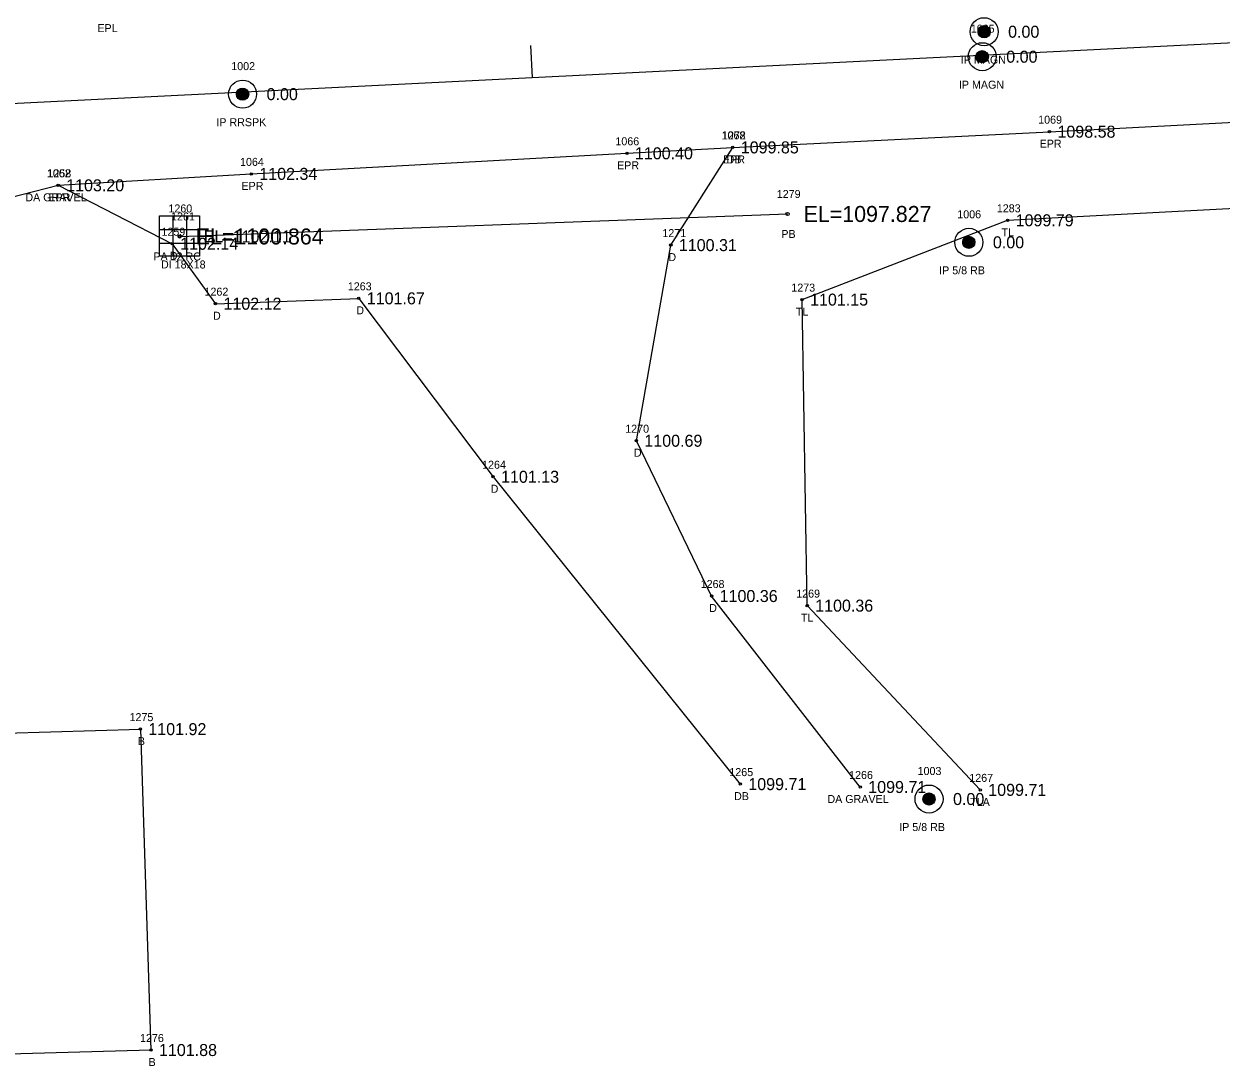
# Model space of a CAD drawing. Extents: x 1539151 to 1541799, y 1198646 to 1201165.
# Drawn here: x 1539429.9 to 1539579.5, y 1199231.9 to 1199362.1 of the extents above; entities that cross this region are included whole.
import ezdxf

# ---------------------------------------------------------------- set-up
doc = ezdxf.new("R2010")
doc.units = 0
for name, color, linetype in [('RD_EX_Bldg', 7, 'Continuous'), ('RD_EX_Bldg_txCode', 7, 'Continuous'), ('RD_EX_DR_Inlet', 7, 'Continuous'), ('RD_EX_DR_Inlet_txCode', 7, 'Continuous'), ('RD_EX_DR_Pipe', 7, 'Continuous'), ('RD_EX_DR_Pipe_txCode', 7, 'Continuous'), ('RD_EX_Driveway', 7, 'Continuous'), ('RD_EX_Driveway_txCode', 7, 'Continuous'), ('RD_EX_DV_Prop_txCode', 7, 'Continuous'), ('RD_EX_DV_PropPin', 7, 'Continuous'), ('RD_EX_Road', 7, 'Continuous'), ('RD_EX_Road_txCode', 7, 'Continuous'), ('RD_EX_TX_Bldg_ELEV', 7, 'Continuous'), ('RD_EX_TX_DR_Inlet_ELEV', 7, 'Continuous'), ('RD_EX_TX_Driveway_ELEV', 7, 'Continuous'), ('RD_EX_TX_DV_Prop_ELEV', 7, 'Continuous'), ('RD_EX_TX_Road_ELEV', 7, 'Continuous'), ('RD_EX_TX_VEG_ELEV', 7, 'Continuous'), ('RD_EX_VEG', 7, 'Continuous'), ('RD_EX_VEG_txCode', 7, 'Continuous'), ('RD_HC_Cl', 7, 'Continuous'), ('RD_HC_Data_Tic', 7, 'Continuous'), ('RD_SMD_Locator', 7, 'Continuous'), ('RD_TX_Pipe_ElevEX', 7, 'Continuous')]:
    doc.layers.add(name, color=color, linetype=linetype)

msp = doc.modelspace()

# ---------------------------------------------------------------- linework, layer by layer
at = {"layer": 'RD_EX_Bldg'}
msp.add_lwpolyline([(1539416.25, 1199273.16), (1539444.4, 1199273.98), (1539445.73, 1199233.89), (1539417.59, 1199233.06), (1539416.25, 1199273.16)], dxfattribs=at)
at = {"layer": 'RD_EX_DR_Inlet'}
for p, q in [((1539448.48, 1199338.09), (1539448.48, 1199333.09)), ((1539450.18, 1199338.09), (1539450.18, 1199333.09)), ((1539446.78, 1199336.39), (1539451.78, 1199336.39)), ((1539446.78, 1199334.69), (1539451.78, 1199334.69))]:
    msp.add_line(p, q, dxfattribs=at)
msp.add_lwpolyline([(1539446.78, 1199333.09), (1539446.78, 1199338.09), (1539451.78, 1199338.09), (1539451.78, 1199333.09)], close=True, dxfattribs=at)
at = {"layer": 'RD_EX_DR_Pipe'}
msp.add_line((1539449.32, 1199335.53), (1539525.29, 1199338.34), dxfattribs=at)
at = {"layer": 'RD_EX_Driveway'}
for points in [[(1539534.37, 1199266.75), (1539515.8, 1199290.61), (1539506.39, 1199310.01), (1539510.7, 1199334.45), (1539518.44, 1199346.66)], [(1539434.13, 1199341.92), (1539448.38, 1199334.62), (1539453.79, 1199327.13), (1539471.7, 1199327.8), (1539488.48, 1199305.51), (1539519.38, 1199267.11)]]:
    msp.add_lwpolyline(points, dxfattribs=at)
at = {"layer": 'RD_EX_DV_PropPin'}
for p, q in [((1539549.11, 1199360.92), (1539549.11, 1199361.31)), ((1539549.15, 1199360.81), (1539549.15, 1199361.41)), ((1539549.18, 1199360.74), (1539549.18, 1199361.48)), ((1539549.22, 1199360.69), (1539549.22, 1199361.54)), ((1539549.25, 1199360.64), (1539549.25, 1199361.59)), ((1539549.29, 1199360.6), (1539549.29, 1199361.63)), ((1539549.32, 1199360.56), (1539549.32, 1199361.66)), ((1539549.36, 1199360.53), (1539549.36, 1199361.69)), ((1539549.39, 1199360.5), (1539549.39, 1199361.72)), ((1539549.43, 1199360.48), (1539549.43, 1199361.75)), ((1539549.46, 1199360.46), (1539549.46, 1199361.77)), ((1539549.5, 1199360.44), (1539549.5, 1199361.79)), ((1539549.53, 1199360.42), (1539549.53, 1199361.8)), ((1539549.57, 1199360.4), (1539549.57, 1199361.82)), ((1539549.6, 1199360.39), (1539549.6, 1199361.83)), ((1539549.64, 1199360.38), (1539549.64, 1199361.84)), ((1539549.67, 1199360.37), (1539549.67, 1199361.85)), ((1539549.71, 1199360.36), (1539549.71, 1199361.86)), ((1539549.74, 1199360.36), (1539549.74, 1199361.87)), ((1539549.78, 1199360.35), (1539549.78, 1199361.87)), ((1539549.81, 1199360.35), (1539549.81, 1199361.87)), ((1539549.85, 1199360.35), (1539549.85, 1199361.87)), ((1539549.88, 1199360.35), (1539549.88, 1199361.87)), ((1539549.92, 1199360.35), (1539549.92, 1199361.87)), ((1539549.95, 1199360.36), (1539549.95, 1199361.87)), ((1539549.99, 1199360.36), (1539549.99, 1199361.86)), ((1539550.02, 1199360.37), (1539550.02, 1199361.85)), ((1539550.06, 1199360.38), (1539550.06, 1199361.84)), ((1539550.09, 1199360.39), (1539550.09, 1199361.83)), ((1539550.13, 1199360.4), (1539550.13, 1199361.82)), ((1539550.16, 1199360.42), (1539550.16, 1199361.8)), ((1539550.2, 1199360.44), (1539550.2, 1199361.79)), ((1539550.23, 1199360.46), (1539550.23, 1199361.77)), ((1539550.27, 1199360.48), (1539550.27, 1199361.75)), ((1539550.3, 1199360.5), (1539550.3, 1199361.72)), ((1539550.34, 1199360.53), (1539550.34, 1199361.69)), ((1539550.37, 1199360.56), (1539550.37, 1199361.66)), ((1539550.41, 1199360.6), (1539550.41, 1199361.63)), ((1539550.44, 1199360.64), (1539550.44, 1199361.59)), ((1539550.48, 1199360.69), (1539550.48, 1199361.54)), ((1539550.51, 1199360.74), (1539550.51, 1199361.48)), ((1539550.55, 1199360.81), (1539550.55, 1199361.41)), ((1539550.58, 1199360.92), (1539550.58, 1199361.31)), ((1539548.88, 1199357.8), (1539548.88, 1199358.19)), ((1539548.92, 1199357.69), (1539548.92, 1199358.29)), ((1539548.95, 1199357.62), (1539548.95, 1199358.36)), ((1539548.99, 1199357.57), (1539548.99, 1199358.42)), ((1539549.02, 1199357.52), (1539549.02, 1199358.47)), ((1539549.06, 1199357.48), (1539549.06, 1199358.51)), ((1539549.09, 1199357.44), (1539549.09, 1199358.54)), ((1539549.13, 1199357.41), (1539549.13, 1199358.57)), ((1539549.16, 1199357.38), (1539549.16, 1199358.6)), ((1539549.2, 1199357.36), (1539549.2, 1199358.63)), ((1539549.23, 1199357.34), (1539549.23, 1199358.65)), ((1539549.27, 1199357.32), (1539549.27, 1199358.67)), ((1539549.3, 1199357.3), (1539549.3, 1199358.68)), ((1539549.34, 1199357.28), (1539549.34, 1199358.7)), ((1539549.37, 1199357.27), (1539549.37, 1199358.71)), ((1539549.41, 1199357.26), (1539549.41, 1199358.72)), ((1539549.44, 1199357.25), (1539549.44, 1199358.73)), ((1539549.48, 1199357.24), (1539549.48, 1199358.74)), ((1539549.51, 1199357.24), (1539549.51, 1199358.75)), ((1539549.55, 1199357.23), (1539549.55, 1199358.75)), ((1539549.58, 1199357.23), (1539549.58, 1199358.75)), ((1539549.62, 1199357.23), (1539549.62, 1199358.75)), ((1539549.65, 1199357.23), (1539549.65, 1199358.75)), ((1539549.69, 1199357.23), (1539549.69, 1199358.75)), ((1539549.72, 1199357.24), (1539549.72, 1199358.75)), ((1539549.76, 1199357.24), (1539549.76, 1199358.74)), ((1539549.79, 1199357.25), (1539549.79, 1199358.73)), ((1539549.83, 1199357.26), (1539549.83, 1199358.72)), ((1539549.86, 1199357.27), (1539549.86, 1199358.71)), ((1539549.9, 1199357.28), (1539549.9, 1199358.7)), ((1539549.93, 1199357.3), (1539549.93, 1199358.68)), ((1539549.97, 1199357.32), (1539549.97, 1199358.67)), ((1539550, 1199357.34), (1539550, 1199358.65)), ((1539550.04, 1199357.36), (1539550.04, 1199358.63)), ((1539550.07, 1199357.38), (1539550.07, 1199358.6)), ((1539550.11, 1199357.41), (1539550.11, 1199358.57)), ((1539550.14, 1199357.44), (1539550.14, 1199358.54)), ((1539550.18, 1199357.48), (1539550.18, 1199358.51)), ((1539550.21, 1199357.52), (1539550.21, 1199358.47)), ((1539550.25, 1199357.57), (1539550.25, 1199358.42)), ((1539550.28, 1199357.62), (1539550.28, 1199358.36)), ((1539550.32, 1199357.69), (1539550.32, 1199358.29)), ((1539550.35, 1199357.8), (1539550.35, 1199358.19)), ((1539456.45, 1199353.11), (1539456.45, 1199353.51)), ((1539456.48, 1199353.01), (1539456.48, 1199353.61)), ((1539456.52, 1199352.94), (1539456.52, 1199353.68)), ((1539456.55, 1199352.88), (1539456.55, 1199353.74)), ((1539456.59, 1199352.84), (1539456.59, 1199353.78)), ((1539456.62, 1199352.79), (1539456.62, 1199353.82)), ((1539456.66, 1199352.76), (1539456.66, 1199353.86)), ((1539456.69, 1199352.73), (1539456.69, 1199353.89)), ((1539456.73, 1199352.7), (1539456.73, 1199353.92)), ((1539456.76, 1199352.67), (1539456.76, 1199353.94)), ((1539456.8, 1199352.65), (1539456.8, 1199353.97)), ((1539456.83, 1199352.63), (1539456.83, 1199353.98)), ((1539456.87, 1199352.62), (1539456.87, 1199354)), ((1539456.9, 1199352.6), (1539456.9, 1199354.02)), ((1539456.94, 1199352.59), (1539456.94, 1199354.03)), ((1539456.97, 1199352.58), (1539456.97, 1199354.04)), ((1539457.01, 1199352.57), (1539457.01, 1199354.05)), ((1539457.04, 1199352.56), (1539457.04, 1199354.06)), ((1539457.08, 1199352.56), (1539457.08, 1199354.06)), ((1539457.11, 1199352.55), (1539457.11, 1199354.07)), ((1539457.15, 1199352.55), (1539457.15, 1199354.07)), ((1539457.18, 1199352.55), (1539457.18, 1199354.07)), ((1539457.22, 1199352.55), (1539457.22, 1199354.07)), ((1539457.25, 1199352.55), (1539457.25, 1199354.07)), ((1539457.29, 1199352.56), (1539457.29, 1199354.06)), ((1539457.32, 1199352.56), (1539457.32, 1199354.06)), ((1539457.36, 1199352.57), (1539457.36, 1199354.05)), ((1539457.39, 1199352.58), (1539457.39, 1199354.04)), ((1539457.43, 1199352.59), (1539457.43, 1199354.03)), ((1539457.46, 1199352.6), (1539457.46, 1199354.02)), ((1539457.5, 1199352.62), (1539457.5, 1199354)), ((1539457.53, 1199352.63), (1539457.53, 1199353.98)), ((1539457.57, 1199352.65), (1539457.57, 1199353.97)), ((1539457.6, 1199352.67), (1539457.6, 1199353.94)), ((1539457.64, 1199352.7), (1539457.64, 1199353.92)), ((1539457.67, 1199352.73), (1539457.67, 1199353.89)), ((1539457.71, 1199352.76), (1539457.71, 1199353.86)), ((1539457.74, 1199352.79), (1539457.74, 1199353.82)), ((1539457.78, 1199352.84), (1539457.78, 1199353.78)), ((1539457.81, 1199352.88), (1539457.81, 1199353.74)), ((1539457.85, 1199352.94), (1539457.85, 1199353.68)), ((1539457.88, 1199353.01), (1539457.88, 1199353.61)), ((1539457.92, 1199353.11), (1539457.92, 1199353.51)), ((1539547.71, 1199334.08), (1539547.71, 1199335.52)), ((1539547.74, 1199334.06), (1539547.74, 1199335.53)), ((1539547.78, 1199334.06), (1539547.78, 1199335.54)), ((1539547.81, 1199334.05), (1539547.81, 1199335.54)), ((1539547.85, 1199334.04), (1539547.85, 1199335.55)), ((1539547.88, 1199334.04), (1539547.88, 1199335.55)), ((1539547.92, 1199334.04), (1539547.92, 1199335.56)), ((1539547.95, 1199334.04), (1539547.95, 1199335.56)), ((1539547.99, 1199334.04), (1539547.99, 1199335.56)), ((1539548.02, 1199334.04), (1539548.02, 1199335.55)), ((1539548.06, 1199334.04), (1539548.06, 1199335.55)), ((1539548.09, 1199334.05), (1539548.09, 1199335.54)), ((1539548.13, 1199334.06), (1539548.13, 1199335.54)), ((1539548.16, 1199334.06), (1539548.16, 1199335.53)), ((1539548.2, 1199334.08), (1539548.2, 1199335.52)), ((1539547.21, 1199334.6), (1539547.21, 1199334.99)), ((1539547.25, 1199334.5), (1539547.25, 1199335.09)), ((1539547.29, 1199334.43), (1539547.29, 1199335.17)), ((1539547.32, 1199334.37), (1539547.32, 1199335.22)), ((1539547.36, 1199334.32), (1539547.36, 1199335.27)), ((1539547.39, 1199334.28), (1539547.39, 1199335.31)), ((1539547.43, 1199334.25), (1539547.43, 1199335.35)), ((1539547.46, 1199334.21), (1539547.46, 1199335.38)), ((1539547.5, 1199334.19), (1539547.5, 1199335.41)), ((1539547.53, 1199334.16), (1539547.53, 1199335.43)), ((1539547.57, 1199334.14), (1539547.57, 1199335.45)), ((1539547.6, 1199334.12), (1539547.6, 1199335.47)), ((1539547.64, 1199334.1), (1539547.64, 1199335.49)), ((1539547.67, 1199334.09), (1539547.67, 1199335.5)), ((1539548.23, 1199334.09), (1539548.23, 1199335.5)), ((1539548.27, 1199334.1), (1539548.27, 1199335.49)), ((1539548.3, 1199334.12), (1539548.3, 1199335.47)), ((1539548.34, 1199334.14), (1539548.34, 1199335.45)), ((1539548.37, 1199334.16), (1539548.37, 1199335.43)), ((1539548.41, 1199334.19), (1539548.41, 1199335.41)), ((1539548.44, 1199334.21), (1539548.44, 1199335.38)), ((1539548.48, 1199334.25), (1539548.48, 1199335.35)), ((1539548.51, 1199334.28), (1539548.51, 1199335.31)), ((1539548.55, 1199334.32), (1539548.55, 1199335.27)), ((1539548.58, 1199334.37), (1539548.58, 1199335.22)), ((1539548.62, 1199334.43), (1539548.62, 1199335.17)), ((1539548.65, 1199334.5), (1539548.65, 1199335.09)), ((1539548.69, 1199334.6), (1539548.69, 1199334.99)), ((1539542.23, 1199265.06), (1539542.23, 1199265.45)), ((1539542.27, 1199264.96), (1539542.27, 1199265.55)), ((1539542.3, 1199264.88), (1539542.3, 1199265.62)), ((1539542.34, 1199264.83), (1539542.34, 1199265.68)), ((1539542.37, 1199264.78), (1539542.37, 1199265.73)), ((1539542.41, 1199264.74), (1539542.41, 1199265.77)), ((1539542.44, 1199264.7), (1539542.44, 1199265.8)), ((1539542.48, 1199264.67), (1539542.48, 1199265.84)), ((1539542.51, 1199264.64), (1539542.51, 1199265.86)), ((1539542.55, 1199264.62), (1539542.55, 1199265.89)), ((1539542.58, 1199264.6), (1539542.58, 1199265.91)), ((1539542.62, 1199264.58), (1539542.62, 1199265.93)), ((1539542.65, 1199264.56), (1539542.65, 1199265.95)), ((1539542.69, 1199264.55), (1539542.69, 1199265.96)), ((1539542.72, 1199264.53), (1539542.72, 1199265.97)), ((1539542.76, 1199264.52), (1539542.76, 1199265.99)), ((1539542.79, 1199264.51), (1539542.79, 1199265.99)), ((1539542.83, 1199264.51), (1539542.83, 1199266)), ((1539542.86, 1199264.5), (1539542.86, 1199266.01)), ((1539542.9, 1199264.5), (1539542.9, 1199266.01)), ((1539542.93, 1199264.49), (1539542.93, 1199266.01)), ((1539542.97, 1199264.49), (1539542.97, 1199266.02)), ((1539543, 1199264.49), (1539543, 1199266.01)), ((1539543.04, 1199264.5), (1539543.04, 1199266.01)), ((1539543.07, 1199264.5), (1539543.07, 1199266.01)), ((1539543.11, 1199264.51), (1539543.11, 1199266)), ((1539543.14, 1199264.51), (1539543.14, 1199265.99)), ((1539543.18, 1199264.52), (1539543.18, 1199265.99)), ((1539543.21, 1199264.53), (1539543.21, 1199265.97)), ((1539543.25, 1199264.55), (1539543.25, 1199265.96)), ((1539543.28, 1199264.56), (1539543.28, 1199265.95)), ((1539543.32, 1199264.58), (1539543.32, 1199265.93)), ((1539543.35, 1199264.6), (1539543.35, 1199265.91)), ((1539543.39, 1199264.62), (1539543.39, 1199265.89)), ((1539543.42, 1199264.64), (1539543.42, 1199265.86)), ((1539543.46, 1199264.67), (1539543.46, 1199265.84)), ((1539543.49, 1199264.7), (1539543.49, 1199265.8)), ((1539543.53, 1199264.74), (1539543.53, 1199265.77)), ((1539543.56, 1199264.78), (1539543.56, 1199265.73)), ((1539543.6, 1199264.83), (1539543.6, 1199265.68)), ((1539543.63, 1199264.88), (1539543.63, 1199265.62)), ((1539543.67, 1199264.96), (1539543.67, 1199265.55)), ((1539543.7, 1199265.06), (1539543.7, 1199265.45))]:
    msp.add_line(p, q, dxfattribs=at)
for centre, radius in [((1539549.85, 1199361.11), 1.75), ((1539549.85, 1199361.11), 0.761), ((1539549.62, 1199357.99), 1.75), ((1539549.62, 1199357.99), 0.761), ((1539457.18, 1199353.31), 1.75), ((1539457.18, 1199353.31), 0.761), ((1539547.95, 1199334.8), 1.75), ((1539547.95, 1199334.8), 0.761), ((1539542.97, 1199265.25), 1.75), ((1539542.97, 1199265.25), 0.761)]:
    msp.add_circle(centre, radius, dxfattribs=at)
at = {"layer": 'RD_EX_Road'}
msp.add_lwpolyline([(1539376.14, 1199238.5), (1539389.65, 1199292.82), (1539395.62, 1199315.5), (1539405.98, 1199330.34), (1539420.48, 1199338.44), (1539434.13, 1199341.92), (1539458.27, 1199343.35), (1539505.21, 1199345.92), (1539518.44, 1199346.66), (1539558.02, 1199348.62), (1539607.46, 1199351.19), (1539654.3, 1199353.64), (1539676.57, 1199355), (1539708.42, 1199356.93), (1539757.47, 1199359.08), (1539779.44, 1199360.44), (1539802.8, 1199361.54), (1539858.43, 1199364.46), (1539908.44, 1199366.95), (1539925.86, 1199367.85), (1539963.35, 1199372.53)], dxfattribs=at)
at = {"layer": 'RD_EX_VEG'}
msp.add_lwpolyline([(1539549.37, 1199266.39), (1539527.74, 1199289.41), (1539527.1, 1199327.64), (1539552.79, 1199337.55), (1539657.87, 1199343.12), (1539645.98, 1199330.41), (1539593.79, 1199322.21), (1539586.84, 1199300.32), (1539607.86, 1199270.31)], dxfattribs=at)
at = {"layer": 'RD_HC_Cl'}
msp.add_line((1539393.53, 1199350.4), (1539900.86, 1199375.77), dxfattribs=at)
at = {"layer": 'RD_HC_Data_Tic'}
msp.add_line((1539493.41, 1199355.4), (1539493.21, 1199359.39), dxfattribs=at)
at = {"layer": 'RD_SMD_Locator'}
for centre, radius in [((1539549.85, 1199361.11), 0.15), ((1539549.62, 1199357.99), 0.15), ((1539457.18, 1199353.31), 0.15), ((1539558.02, 1199348.62), 0.15), ((1539505.21, 1199345.92), 0.15), ((1539518.44, 1199346.66), 0.15), ((1539518.44, 1199346.66), 0.15), ((1539458.27, 1199343.35), 0.15), ((1539434.13, 1199341.92), 0.15), ((1539434.13, 1199341.92), 0.15), ((1539525.29, 1199338.34), 0.2), ((1539552.79, 1199337.55), 0.15), ((1539449.32, 1199335.53), 0.2), ((1539449.32, 1199335.53), 0.15), ((1539448.38, 1199334.62), 0.15), ((1539510.7, 1199334.45), 0.15), ((1539547.95, 1199334.8), 0.15), ((1539453.79, 1199327.13), 0.15), ((1539471.7, 1199327.8), 0.15), ((1539527.1, 1199327.64), 0.15), ((1539506.39, 1199310.01), 0.15), ((1539488.48, 1199305.51), 0.15), ((1539515.8, 1199290.61), 0.15), ((1539527.74, 1199289.41), 0.15), ((1539444.4, 1199273.98), 0.15), ((1539519.38, 1199267.11), 0.15), ((1539534.37, 1199266.75), 0.15), ((1539542.97, 1199265.25), 0.15), ((1539549.37, 1199266.39), 0.15), ((1539445.73, 1199233.89), 0.15)]:
    msp.add_circle(centre, radius, dxfattribs=at)

# ---------------------------------------------------------------- texts
at = {"layer": 'RD_EX_Bldg_txCode'}
for s, p in [('1275', (1539443.05, 1199274.98)), ('B', (1539444.09, 1199271.98)), ('1276', (1539444.36, 1199234.89)), ('B', (1539445.43, 1199231.89))]:
    msp.add_text(s, height=1, dxfattribs=at).set_placement(p)
at = {"layer": 'RD_EX_DR_Inlet_txCode'}
for s, p in [('1260', (1539447.91, 1199338.53)), ('DI 18X18', (1539446.98, 1199331.53))]:
    msp.add_text(s, height=1, dxfattribs=at).set_placement(p)
at = {"layer": 'RD_EX_DR_Pipe_txCode'}
for s, p in [('1279', (1539523.94, 1199340.34)), ('1261', (1539448.24, 1199337.53)), ('PB', (1539524.51, 1199335.34)), ('PA 12 RC', (1539446.03, 1199332.53))]:
    msp.add_text(s, height=1, dxfattribs=at).set_placement(p)
at = {"layer": 'RD_EX_Driveway_txCode'}
for s, p in [('1272', (1539517.1, 1199347.66)), ('DB', (1539517.67, 1199344.66)), ('1258', (1539432.79, 1199342.92)), ('DA GRAVEL', (1539430.03, 1199339.92)), ('1259', (1539447.04, 1199335.62)), ('1271', (1539509.64, 1199335.45)), ('D', (1539448.08, 1199332.62)), ('D', (1539510.39, 1199332.45)), ('1263', (1539470.33, 1199328.8)), ('1262', (1539452.42, 1199328.13)), ('D', (1539471.39, 1199325.8)), ('D', (1539453.48, 1199325.13)), ('1270', (1539505, 1199311.01)), ('D', (1539506.08, 1199308.01)), ('1264', (1539487.11, 1199306.51)), ('D', (1539488.18, 1199303.51)), ('1268', (1539514.43, 1199291.61)), ('D', (1539515.49, 1199288.61)), ('1265', (1539518.01, 1199268.11)), ('1266', (1539532.98, 1199267.75)), ('DB', (1539518.6, 1199265.11)), ('DA GRAVEL', (1539530.27, 1199264.75))]:
    msp.add_text(s, height=1, dxfattribs=at).set_placement(p)
at = {"layer": 'RD_EX_DV_Prop_txCode'}
for s, p in [('1005', (1539548.19, 1199360.99)), ('IP MAGN', (1539546.94, 1199357.11)), ('1002', (1539455.76, 1199356.31)), ('IP MAGN', (1539546.7, 1199353.99)), ('IP RRSPK', (1539453.9, 1199349.31)), ('1006', (1539546.5, 1199337.8)), ('IP 5/8 RB', (1539544.23, 1199330.8)), ('1003', (1539541.54, 1199268.25)), ('IP 5/8 RB', (1539539.24, 1199261.25))]:
    msp.add_text(s, height=1, dxfattribs=at).set_placement(p)
at = {"layer": 'RD_EX_Road_txCode'}
for s, p in [('EPL', (1539439.03, 1199361.06)), ('1069', (1539556.61, 1199349.62)), ('1066', (1539503.77, 1199346.92)), ('1068', (1539517.04, 1199347.66)), ('EPR', (1539556.79, 1199346.62)), ('1064', (1539456.86, 1199344.35)), ('EPR', (1539503.98, 1199343.92)), ('EPR', (1539517.22, 1199344.66)), ('1062', (1539432.72, 1199342.92)), ('EPR', (1539457.04, 1199341.35)), ('EPR', (1539432.9, 1199339.92))]:
    msp.add_text(s, height=1, dxfattribs=at).set_placement(p)
at = {"layer": 'RD_EX_TX_Bldg_ELEV'}
for s, p in [('1101.92', (1539445.4, 1199273.23)), ('1101.88', (1539446.73, 1199233.14))]:
    msp.add_text(s, height=1.5, dxfattribs=at).set_placement(p)
at = {"layer": 'RD_EX_TX_DR_Inlet_ELEV'}
msp.add_text('EL=1102.11', height=1.5, dxfattribs=at).set_placement((1539452.32, 1199334.78))
at = {"layer": 'RD_EX_TX_Driveway_ELEV'}
for s, p in [('1099.85', (1539519.44, 1199345.91)), ('1103.20', (1539435.13, 1199341.17)), ('1102.14', (1539449.38, 1199333.87)), ('1100.31', (1539511.7, 1199333.7)), ('1101.67', (1539472.7, 1199327.05)), ('1102.12', (1539454.79, 1199326.38)), ('1100.69', (1539507.39, 1199309.26)), ('1101.13', (1539489.48, 1199304.76)), ('1100.36', (1539516.8, 1199289.86)), ('1099.71', (1539520.38, 1199266.36)), ('1099.71', (1539535.37, 1199266))]:
    msp.add_text(s, height=1.5, dxfattribs=at).set_placement(p)
at = {"layer": 'RD_EX_TX_DV_Prop_ELEV'}
for p in [(1539552.85, 1199360.36), (1539552.62, 1199357.24), (1539460.18, 1199352.56), (1539550.95, 1199334.05), (1539545.97, 1199264.5)]:
    msp.add_text('0.00', height=1.5, dxfattribs=at).set_placement(p)
at = {"layer": 'RD_EX_TX_Road_ELEV'}
for s, p in [('1098.58', (1539559.02, 1199347.87)), ('1100.40', (1539506.21, 1199345.17)), ('1099.85', (1539519.44, 1199345.91)), ('1102.34', (1539459.27, 1199342.6)), ('1103.20', (1539435.13, 1199341.17))]:
    msp.add_text(s, height=1.5, dxfattribs=at).set_placement(p)
at = {"layer": 'RD_EX_TX_VEG_ELEV'}
for s, p in [('1099.79', (1539553.79, 1199336.8)), ('1101.15', (1539528.1, 1199326.89)), ('1100.36', (1539528.74, 1199288.66)), ('1099.71', (1539550.37, 1199265.64))]:
    msp.add_text(s, height=1.5, dxfattribs=at).set_placement(p)
at = {"layer": 'RD_EX_VEG_txCode'}
for s, p in [('1283', (1539551.44, 1199338.55)), ('TL', (1539552.02, 1199335.55)), ('1273', (1539525.76, 1199328.64)), ('TL', (1539526.33, 1199325.64)), ('1269', (1539526.37, 1199290.41)), ('TL', (1539526.97, 1199287.41)), ('1267', (1539548, 1199267.39)), ('TLA', (1539548.11, 1199264.39))]:
    msp.add_text(s, height=1, dxfattribs=at).set_placement(p)
at = {"layer": 'RD_TX_Pipe_ElevEX'}
for s, p in [('EL=1097.827', (1539527.29, 1199337.34)), ('EL=1100.864', (1539451.32, 1199334.53))]:
    msp.add_text(s, height=2, dxfattribs=at).set_placement(p)

doc.saveas('drawing.dxf')
